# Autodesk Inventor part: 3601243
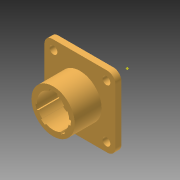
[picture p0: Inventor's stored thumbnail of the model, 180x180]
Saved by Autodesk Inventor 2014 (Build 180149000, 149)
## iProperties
Company: Autodesk
GlobalPropertyList: <PropertyList/>
Shininess: 64.0
Length Units: 11272
Angle Units: 11279
Time Units: 11290
Mass Units: 11286
Length Display Precision: 3
Angle Display Precision: 2
Compacted: True
Part Number: 3601243
Document SubType Name: Modeling
Created: 2003-10
Designer: Garin Gardiner
Manufacturer: Standard
Standards Organization: Custom
Project: AIP
Description: AMP 3
Density: 1 g/cm^3
Mass: 4.21933 g
Surface Area: 38.9487 cm^2
Volume: 4.21933 cm^3
Material: Generic
Appearance: Orange (Pale)
Density: 0.0
Volumn: 0.0
Area: 0.0
PropertySet Name: Model Information
Control State: 0
Master: False
Checked Out: False
Subject: AMP 3
Author: Garin Gardiner
Revision Number: 0
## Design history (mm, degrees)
sketch "Sketch1"
  geometry: L1 (14.288, 14.287)-(-14.287, 14.287); L2 (-14.287, 14.287)-(-14.288, -14.287); L3 (-14.288, -14.287)-(14.288, -14.287); L4 (14.288, -14.287)-(14.288, 14.287); 3 further points
  constraints: 8 end point, 2 midpoint, 2 parallel, 2 perpendicular, 1 horizontal, 1 horizontal alignment, 1 vertical alignment
  dimensions: "d0" = 28.575 distance of L1.start L1.end
extrude "Extrusion1" new body sketch "Sketch1" distance "d1" = 2.3876; taper "d2" = 0 deg
fillet "Fillet1" dims "d3" = 3.175
sketch "Sketch2"
  geometry: L1 (11.112, -14.287)-(-11.113, -14.287) reference; L2 (14.288, 11.113)-(14.288, -11.113) reference; L3 (-11.112, 14.287)-(11.113, 14.287) reference; L4 (-14.288, -11.113)-(-14.287, 11.113) reference; 4 further points
  constraints: 2 horizontal alignment, 2 vertical alignment
  dimensions: "d4" = 3.6322 distance from line of L4 point (-10.655, 10.655); "d5" = 3.6322 distance from line of L3 point (-10.655, 10.655) (= d4); "d6" = 3.6322 distance from line of L1 point (-10.655, -10.655) (= d4); "d7" = 3.6322 distance from line of L2 point (10.655, -10.655) (= d4)
hole "Hole1" sketch "Sketch2" at (-10.655, 10.655), (10.655, 10.655), (10.655, -10.655), (-10.655, -10.655) diameter "d8" = 3.1496; stored, may be unused: countersink angle "d12" = 82 deg, drill point angle "d14" = 118 deg; dims "d9" = 12.7, "d10" = 9.525, "d11" = 6.35, "d13" = 19.05
sketch "Sketch3"
  geometry: L1 (14.288, 11.113)-(14.288, -11.113) reference; L2 (-11.112, 14.287)-(11.113, 14.287) reference; C1 r 8.712 at (0, 0); 2 further points
  constraints: 2 midpoint, 1 centre point, 1 horizontal alignment, 1 vertical alignment
  dimensions: "d15" = 17.4244 diameter of C1
extrude "Extrusion2" join sketch "Sketch3" distance "d16" = 10.795; taper "d17" = 0 deg
sketch "Sketch4"
  geometry: C1 r 8.712 at (0, 0) reference; C2 r 6.477 at (0, 0)
  constraints: 1 centre point, 1 coincident
  dimensions: "d19" = 6.477 radius of C2
extrude "Extrusion3" cut sketch "Sketch4" distance "d20" = 8.89; taper "d21" = 0 deg
sketch "Sketch5"
  geometry: L1 (-1.651, 6.263)-(-1.651, 6.957); L2 (1.651, 6.263)-(1.651, 6.957); C1 r 8.712 at (0, 0) reference; A1 r 6.477 centre (0, 0) between (-1.651, 6.263) and (1.651, 6.263) reference; A2 r 7.15 centre (0, 0) between (-1.651, 6.957) and (1.651, 6.957)
  constraints: 4 end point, 4 point on circle, 2 parallel, 1 centre point, 1 coincident, 1 vertical
  dimensions: "d22" = 7.1501 radius of A2; "d23" = 3.302 distance between parallel lines of L2 L1
extrude "Extrusion4" cut sketch "Sketch5" stored distance "d24" = 8.89; taper "d25" = 0 deg
sketch "Sketch6"
  geometry: L1 (1.651, 6.957)-(1.651, 6.263) reference; L2 (-1.651, 6.263)-(-1.651, 6.957) reference; L3 (-6.435, -0.738)-(-7.091, -0.914); L4 (-5.942, -2.578)-(-6.598, -2.754); L5 (-4.455, -4.702)-(-4.845, -5.258); L6 (-3.284, -6.351)-(-2.894, -5.794); L7 (2.894, -5.794)-(3.284, -6.351); L8 (4.455, -4.702)-(4.845, -5.258); L9 (6.465, 0.391)-(7.142, 0.331); L10 (6.299, -1.507)-(6.976, -1.566); C1 r 8.712 at (0, 0) reference; A1 r 7.15 centre (0, 0) between (1.651, 6.957) and (-1.651, 6.957) reference; 2 further points
  constraints: 16 end point, 8 parallel, 1 coincident, 21 other
  dimensions: "d26" = 105 deg angle of L2 L3; "d27" = 1.905 distance between parallel lines of L4 L3; "d30" = 1.905 distance between parallel lines of L6 L5 (= d27); "d31" = 40 deg angle of L4 L5; "d32" = 70 deg angle of L7 L6; "d33" = 1.905 distance between parallel lines of L8 L7 (= d30); "d34" = 1.905 distance between parallel lines of L9 L10 (= d33); "d35" = 50 deg angle of L10 L8
extrude "Extrusion5" cut sketch "Sketch6" stored distance "d28" = 8.89; taper "d29" = 0 deg
sketch "Sketch7"
  geometry: C1 r 5.207 at (0, 0); A1 r 7.15 centre (0, 0) between (1.651, 6.957) and (-1.651, 6.957) reference
  constraints: 1 centre point, 1 coincident
  dimensions: "d36" = 10.414 diameter of C1
extrude "Extrusion6" join sketch "Sketch7" distance "d37" = 0.381; taper "d38" = 0 deg
sketch "Sketch8"
  geometry: L1 (-11.113, 14.287)-(11.112, 14.287) reference; L2 (-14.288, -11.113)-(-14.288, 11.113) reference; C1 r 7.874 at (0, 0); 2 further points
  constraints: 2 midpoint, 1 centre point, 1 horizontal alignment, 1 vertical alignment
  dimensions: "d39" = 15.748 diameter of C1
extrude "Extrusion7" join sketch "Sketch8" distance "d40" = 5.715; taper "d41" = 0 deg
sketch "Sketch9"
  geometry: C1 r 7.874 at (0, 0) reference; C2 r 7.175 at (0, 0)
  constraints: 1 centre point, 1 coincident
  dimensions: "d42" = 7.1755 radius of C2
extrude "Extrusion8" join sketch "Sketch9" distance "d43" = 1.27; taper "d44" = 0 deg
sketch "Sketch10"
  geometry: L1 (-2.095, 5.385)-(-2.095, 6.863); L2 (2.096, 5.385)-(2.096, 6.863); A1 r 7.175 centre (0, 0) between (-2.095, 6.863) and (2.096, 6.863) reference; A2 r 5.778 centre (0, 0) between (-2.095, 5.385) and (2.096, 5.385)
  constraints: 4 end point, 4 point on circle, 2 parallel, 1 centre point, 1 coincident, 1 vertical
  dimensions: "d45" = 5.7785 radius of A2; "d46" = 4.191 distance between parallel lines of L2 L1
extrude "Extrusion9" cut sketch "Sketch10" stored distance "d47" = 1.27; taper "d48" = 0 deg
sketch "Sketch11"
  geometry: C1 r 5.207 at (0, 0) reference; 9 further points
  constraints: 1 coincident, 1 vertical alignment, 9 other
  dimensions: "d49" = 4.3688 distance of point (0, 4.369) point (0, 0); "d52" = 360 deg dimension on C1.centre point (0, 4.369) (derived)
hole "Hole2" sketch "Sketch11" at (0, 0), (0, 4.369), (-3.089, 3.089), (-4.369, 0), (-3.089, -3.089), (0, -4.369), (3.089, -3.089), (4.369, 0), (3.089, 3.089) diameter "d54" = 1.016; stored, may be unused: countersink angle "d58" = 82 deg, drill point angle "d60" = 118 deg; dims "d55" = 12.7, "d56" = 9.525, "d57" = 6.35, "d59" = 19.05
sketch "Sketch12"
  geometry: C1 r 0.508 at (-4.369, 0) reference; C2 r 0.508 at (0, -4.369) reference; C3 r 0.508 at (4.369, 0) reference; C4 r 0.508 at (0, 4.369) reference; C5 r 0.508 at (0, 0) reference; C6 r 0.508 at (3.089, 3.089) reference; C7 r 0.508 at (3.089, -3.089) reference; C8 r 0.508 at (-3.089, -3.089) reference; C9 r 0.508 at (-3.089, 3.089) reference
hole "Hole3" sketch "Sketch12" at (0, 4.369), (-3.089, 3.089), (-4.369, 0), (-3.089, -3.089), (0, 0), (3.089, 3.089), (4.369, 0), (3.089, -3.089), (0, -4.369) diameter "d61" = 2.0828; stored, may be unused: countersink angle "d65" = 82 deg, drill point angle "d67" = 0 deg; dims "d62" = 12.7, "d63" = 9.525, "d64" = 6.35, "d66" = 9.652
sketch "Sketch13"
  geometry: L1 (2.096, 6.863)-(2.096, 5.385) reference; L2 (-1.397, -7.038)-(-1.397, -5.607); L3 (1.397, -7.038)-(1.397, -5.607); A1 r 7.175 centre (0, 0) between (-2.095, 6.863) and (2.096, 6.863) reference; A2 r 5.778 centre (0, 0) between (2.096, 5.385) and (-2.095, 5.385) reference; A3 r 5.778 centre (0, 0) between (2.096, 5.385) and (-1.397, -5.607)
  constraints: 5 point on circle, 4 end point, 3 parallel, 1 centre point, 1 coincident
  dimensions: "d68" = 2.794 distance between parallel lines of L3 L2
extrude "Extrusion10" cut sketch "Sketch13" stored distance "d69" = 25.4; taper "d70" = 0 deg
sketch "Sketch15"
  geometry: L1 (2.87, 5.696)-(4.014, 5.696); L2 (4.014, 5.696)-(4.014, 4.217); L3 (4.014, 4.217)-(2.87, 4.217); L4 (2.87, 4.217)-(2.87, 5.696); L5 (5.77, -0.758)-(5.77, 0.72); L6 (5.77, 0.72)-(6.915, 0.72); L7 (6.915, 0.72)-(6.915, -0.758); L8 (6.915, -0.758)-(5.77, -0.758); L9 (-4.483, 4.122)-(-4.483, 5.601); L10 (-4.483, 5.601)-(-3.338, 5.601); L11 (-3.338, 5.601)-(-3.338, 4.122); L12 (-3.338, 4.122)-(-4.483, 4.122); L13 (2.606, -5.925)-(2.606, -4.447); L14 (2.606, -4.447)-(3.75, -4.447); L15 (3.75, -4.447)-(3.75, -5.925); L16 (3.75, -5.925)-(2.606, -5.925); L17 (-3.708, -5.846)-(-3.708, -4.367); L18 (-3.708, -4.367)-(-2.563, -4.367); L19 (-2.563, -4.367)-(-2.563, -5.846); L20 (-2.563, -5.846)-(-3.708, -5.846); L21 (-0.519, -2.914)-(-0.519, -1.435); L22 (-0.519, -1.435)-(0.625, -1.435); L23 (0.625, -1.435)-(0.625, -2.914); L24 (0.625, -2.914)-(-0.519, -2.914); L25 (-6.837, -0.756)-(-6.837, 0.723); L26 (-6.837, 0.723)-(-5.693, 0.723); L27 (-5.693, 0.723)-(-5.693, -0.756); L28 (-5.693, -0.756)-(-6.837, -0.756)
  constraints: 14 other
emboss "Emboss2" sketch "Sketch15" dims "d4" = 3.6322, "d5" = 3.6322 (= d4), "d6" = 3.6322 (= d4), "d7" = 3.6322 (= d4), "d73" = 0.0254, "d74" = 0
sketch "Sketch25"
  geometry: L1 (-4.322, 2.554)-(-3.178, 2.554); L2 (-3.178, 2.554)-(-3.178, 1.075); L3 (-3.178, 1.075)-(-4.322, 1.075); L4 (-4.322, 1.075)-(-4.322, 2.554); L5 (-4.488, -2.133)-(-4.488, -0.654); L6 (-4.488, -0.654)-(-3.344, -0.654); L7 (-3.344, -0.654)-(-3.344, -2.133); L8 (-3.344, -2.133)-(-4.488, -2.133); L9 (1.41, 2.744)-(1.41, 4.223); L10 (1.41, 4.223)-(2.555, 4.223); L11 (2.555, 4.223)-(2.555, 2.744); L12 (2.555, 2.744)-(1.41, 2.744); L13 (-2.285, -4.582)-(-2.285, -3.103); L14 (-2.285, -3.103)-(-1.14, -3.103); L15 (-1.14, -3.103)-(-1.14, -4.582); L16 (-1.14, -4.582)-(-2.285, -4.582); L17 (0.729, -4.498)-(0.729, -3.019); L18 (0.729, -3.019)-(1.873, -3.019); L19 (1.873, -3.019)-(1.873, -4.498); L20 (1.873, -4.498)-(0.729, -4.498); L21 (-0.614, -2.201)-(-0.614, -0.722); L22 (-0.614, -0.722)-(0.53, -0.722); L23 (0.53, -0.722)-(0.53, -2.201); L24 (0.53, -2.201)-(-0.614, -2.201); L25 (3.514, 0.398)-(3.514, 1.876); L26 (3.514, 1.876)-(4.659, 1.876); L27 (4.659, 1.876)-(4.659, 0.398); L28 (4.659, 0.398)-(3.514, 0.398); L29 (-1.484, 3.22)-(-1.484, 4.699); L30 (-1.484, 4.699)-(-0.34, 4.699); L31 (-0.34, 4.699)-(-0.34, 3.22); L32 (-0.34, 3.22)-(-1.484, 3.22); L33 (3.217, -2.756)-(3.217, -1.277); L34 (3.217, -1.277)-(4.361, -1.277); L35 (4.361, -1.277)-(4.361, -2.756); L36 (4.361, -2.756)-(3.217, -2.756)
  constraints: 18 other
emboss "Emboss3" sketch "Sketch25" dims "d4" = 3.6322, "d5" = 3.6322 (= d4), "d6" = 3.6322 (= d4), "d7" = 3.6322 (= d4), "d76" = 0.0254, "d77" = 0
workpoint "Work Point11"
  workplane "Work Plane2"
  workaxis "Work Axis2"
workpoint "Work Point12"
  workplane "Work Plane3"
  workaxis "Work Axis3"
sketch "Sketch27"
  geometry: C1 r 1.041 at (0, 4.369) reference
node "1"
sketch "Sketch28"
  geometry: C1 r 1.041 at (3.089, 3.089) reference
node "2"
sketch "Sketch29"
  geometry: C1 r 1.041 at (-3.089, 3.089) reference
node "3"
sketch "Sketch30"
  geometry: C1 r 1.041 at (4.369, 0) reference
node "4"
sketch "Sketch31"
  geometry: C1 r 1.041 at (0, 0) reference
node "5"
sketch "Sketch32"
  geometry: C1 r 1.041 at (-4.369, 0) reference
node "6"
sketch "Sketch33"
  geometry: C1 r 1.041 at (3.089, -3.089) reference
node "7"
sketch "Sketch34"
  geometry: C1 r 1.041 at (-3.089, -3.089) reference
node "8"
sketch "Sketch35"
  geometry: C1 r 1.041 at (0, -4.369) reference
node "9"
body "Solid1"
other parameters: "d80" = 4.7752, "d81" = 9.525
